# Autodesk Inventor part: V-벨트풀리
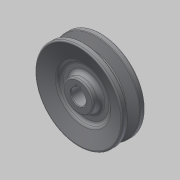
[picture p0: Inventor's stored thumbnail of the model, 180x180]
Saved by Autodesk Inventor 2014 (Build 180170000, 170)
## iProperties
Created: 2016-08
Part Number: V-벨트풀리
Material: 알루미늄 6061
Document SubType Name: Modeling
Designer: mduedu
Density: 2.71 g/cm^3
Appearance: 기본값
Author: mduedu
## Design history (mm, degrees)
sketch "스케치1"
  geometry: L1 (0, 9.5)-(0, -9.5); L2 (0, 9.5)-(35, 9.5); L3 (35, 9.5)-(35, 4.825); L4 (35, 4.825)-(26, 2.074); L5 (26, 2.074)-(26, 0); L6 (0, 0)-(26, 0); L7 (0, -9.5)-(35, -9.5); L8 (35, -9.5)-(35, -4.825); L9 (35, -4.825)-(26, -2.074); L10 (26, -2.074)-(26, 0); L11 (32.3, 9.5)-(32.3, -9.5); 3 further points
  constraints: 22 end point, 6 point on line, 4 perpendicular, 3 symmetric about line, 1 coincident, 1 horizontal alignment, 1 midpoint, 1 parallel, 1 vertical
  dimensions: "d0" = 19 distance of L1.start L1.end; "d2" = 70 diameter of L8 L1; "d4" = 6.3 distance between parallel lines of L10 L11; "d5" = 2.7 distance between parallel lines of L11 L8; "d6" = 8 distance of point (32.3, -4) point (32.3, 4); "d7" = 34 deg angle of L9 L4
revolve "회전1" sketch "스케치1" stored, may be unused: angle "d8" = 90 deg
sketch "스케치2"
  geometry: L1 (-2, 0)-(2, 0); L2 (2, 0)-(2, 7.8); L3 (2, 7.8)-(-2, 7.8); L4 (-2, 7.8)-(-2, 0); C1 r 6 at (0, 0); 2 further points
  constraints: 8 end point, 2 coincident, 2 parallel, 1 centre point, 1 horizontal, 1 midpoint, 1 perpendicular
  dimensions: "d9" = 12 diameter of C1; "d11" = 4 distance of L2.end L3.end; "d12" = 7.8 distance of L1.end L2.end
extrude "돌출1" cut sketch "스케치2" stored distance "d13" = 10; taper "d14" = 0 deg
sketch "스케치3"
  geometry: L1 (35, 4.825)-(26, 2.074) reference; L2 (26, 2.074)-(26, -2.074) reference; L3 (0, 0)-(26, 0); L4 (35, 9.5)-(35, 4.825) reference; L5 (-35, 9.5)-(35, 9.5) reference; L6 (35, 9.5)-(21, 5.22); L7 (21, 5.22)-(21, 3); L8 (21, 3)-(12, 3); L9 (12, 3)-(12, 9.5); L10 (0, 9.5)-(0, -9.5); L11 (5.657, -9.5)-(-6, -9.5) reference; L12 (12, 9.5)-(35, 9.5)
  constraints: 14 end point, 3 midpoint, 2 parallel, 2 perpendicular, 2 point on line, 1 collinear, 1 horizontal
  dimensions: "d15" = 3 distance between parallel lines of L3 L8; "d17" = 42 diameter of L7 L10; "d18" = 24 diameter of L9 L10
revolve "회전2" sketch "스케치3" stored, may be unused: angle "d19" = 90 deg
fillet "모깎기1" dims "d20" = 0.5, "d21" = 1, "d22" = 1
fillet "모깎기2" dims "d23" = 3
fillet "모깎기3" dims "d24" = 3
fillet "모깎기4" dims "d25" = 3
chamfer "모따기1" distance "d26" = 0.5; stored, may be unused: second distance "d27" = 2, angle "d28" = 45 deg
fillet "모깎기5" dims "d29" = 1
node "솔리드1"
mirror "대칭1"
